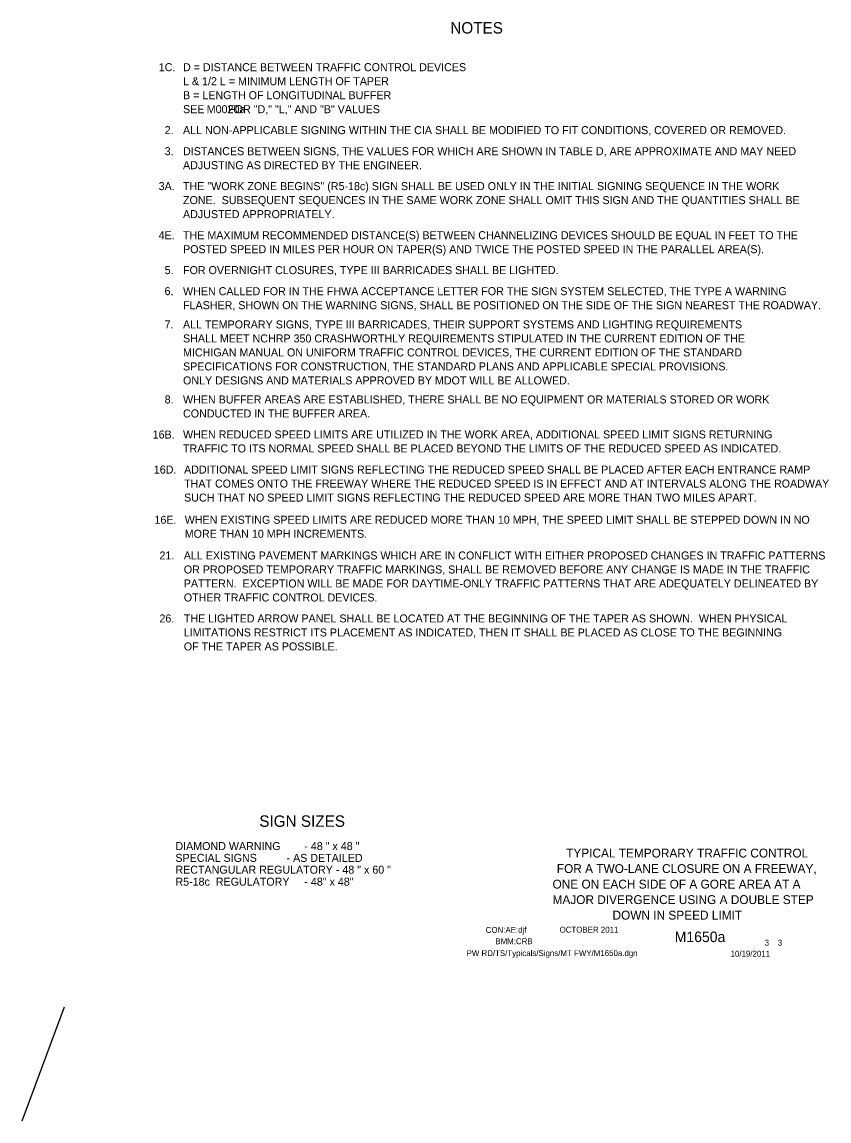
# Model space of a CAD drawing. Extents: x 16512 to 19509, y 5761 to 6974.
# Drawn here: x 18661 to 19509, y 5761 to 6914 of the extents above; entities that cross this region are included whole.
import ezdxf

# ---------------------------------------------------------------- set-up
doc = ezdxf.new("R2010")
doc.units = 0
for name, color, linetype in [('BORDER', 7, 'Continuous'), ('BORDER_SIGNAL_WO', 7, 'Continuous'), ('TYPICAL_TEXT_DIMEN_PR', 7, 'Continuous')]:
    doc.layers.add(name, color=color, linetype=linetype)

msp = doc.modelspace()

# ---------------------------------------------------------------- linework, layer by layer
at = {"layer": 'TYPICAL_TEXT_DIMEN_PR'}
msp.add_line((18705.8, 5880), (18661.5, 5760.5), dxfattribs=at)

# ---------------------------------------------------------------- texts
at = {"layer": 'BORDER'}
for s, p in [('TYPICAL TEMPORARY TRAFFIC CONTROL', (19233.2, 6037.2)), ('FOR A TWO-LANE CLOSURE ON A FREEWAY,', (19223.4, 6020.9)), ('ONE ON EACH SIDE OF A GORE AREA AT A ', (19218.9, 6004.6)), ('MAJOR DIVERGENCE USING A DOUBLE STEP ', (19218.9, 5988.3)), ('DOWN IN SPEED LIMIT', (19281.9, 5972))]:
    msp.add_text(s, height=9.3, dxfattribs=at).set_placement(p)
at = {"layer": 'BORDER_SIGNAL_WO'}
for s, height, p in [('CON:AE:djf  ', 6.2, (19148.7, 5958.1)), ('    OCTOBER 2011    ', 6.2, (19217.1, 5958.3)), ('    M1650a   ', 11, (19330.9, 5948.4)), ('BMM:CRB   ', 6.2, (19158.8, 5946.2)), (' 3    3 ', 6.2, (19439.4, 5944.7)), ('PW RD/TS/Typicals/Signs/MT FWY/M1650a.dgn      ', 6.2, (19128.6, 5933.7)), ('10/19/2011    ', 6.2, (19405.9, 5933.1))]:
    msp.add_text(s, height=height, dxfattribs=at).set_placement(p)
at = {"layer": 'TYPICAL_TEXT_DIMEN_PR'}
for s, height, p in [('NOTES', 12, (19111.5, 6902.3)), ('1C.', 8.4, (18805.2, 6862.8)), ('D = DISTANCE BETWEEN TRAFFIC CONTROL DEVICES', 8.4, (18830.7, 6862.8)), ('L & 1/2 L = MINIMUM LENGTH OF TAPER', 8.4, (18830.7, 6848.1)), ('B = LENGTH OF LONGITUDINAL BUFFER', 8.4, (18830.7, 6833.4)), ('SEE        FOR "D," "L," AND "B" VALUES', 8.4, (18830.7, 6818.7)), ('M0020a', 8.4, (18855.6, 6818.7)), ('2.', 8.4, (18811.4, 6796.7)), ('ALL NON-APPLICABLE SIGNING WITHIN THE CIA SHALL BE MODIFIED TO FIT CONDITIONS, COVERED OR REMOVED.', 8.4, (18830.7, 6796.7)), ('3.', 8.4, (18811.4, 6774.6)), ('DISTANCES BETWEEN SIGNS, THE VALUES FOR WHICH ARE SHOWN IN TABLE D, ARE APPROXIMATE AND MAY NEED', 8.4, (18830.7, 6774.6)), ('ADJUSTING AS DIRECTED BY THE ENGINEER.', 8.4, (18830.7, 6759.9)), ('3A.', 8.4, (18805.1, 6737.9)), ('THE "WORK ZONE BEGINS" (R5-18c) SIGN SHALL BE USED ONLY IN THE INITIAL SIGNING SEQUENCE IN THE WORK', 8.4, (18830.7, 6737.9)), ('ZONE.  SUBSEQUENT SEQUENCES IN THE SAME WORK ZONE SHALL OMIT THIS SIGN AND THE QUANTITIES SHALL BE', 8.4, (18830.7, 6723.2)), ('ADJUSTED APPROPRIATELY.', 8.4, (18830.7, 6708.5)), ('4E.', 8.4, (18805.1, 6686.4)), ('THE MAXIMUM RECOMMENDED DISTANCE(S) BETWEEN CHANNELIZING DEVICES SHOULD BE EQUAL IN FEET TO THE', 8.4, (18830.7, 6686.4)), ('POSTED SPEED IN MILES PER HOUR ON TAPER(S) AND TWICE THE POSTED SPEED IN THE PARALLEL AREA(S).', 8.4, (18830.7, 6671.7)), ('5.', 8.4, (18811.4, 6649.7)), ('FOR OVERNIGHT CLOSURES, TYPE III BARRICADES SHALL BE LIGHTED.', 8.4, (18830.7, 6649.7)), ('6.', 8.4, (18811.3, 6627.6)), ('WHEN CALLED FOR IN THE FHWA ACCEPTANCE LETTER FOR THE SIGN SYSTEM SELECTED, THE TYPE A WARNING ', 8.4, (18830.7, 6627.6)), ('FLASHER, SHOWN ON THE WARNING SIGNS, SHALL BE POSITIONED ON THE SIDE OF THE SIGN NEAREST THE ROADWAY.', 8.4, (18830.7, 6612.9)), ('7.', 8.4, (18811.3, 6592.7)), ('ALL TEMPORARY SIGNS, TYPE III BARRICADES, THEIR SUPPORT SYSTEMS AND LIGHTING REQUIREMENTS', 8.4, (18830.7, 6592.7)), ('SHALL MEET NCHRP 350 CRASHWORTHLY REQUIREMENTS STIPULATED IN THE CURRENT EDITION OF THE', 8.4, (18830.7, 6578)), ('MICHIGAN MANUAL ON UNIFORM TRAFFIC CONTROL DEVICES, THE CURRENT EDITION OF THE STANDARD', 8.4, (18830.7, 6563.3)), ('SPECIFICATIONS FOR CONSTRUCTION, THE STANDARD PLANS AND APPLICABLE SPECIAL PROVISIONS.', 8.4, (18830.7, 6548.6)), ('ONLY DESIGNS AND MATERIALS APPROVED BY MDOT WILL BE ALLOWED.', 8.4, (18830.7, 6533.9)), ('8.', 8.4, (18811.4, 6513.9)), ('WHEN BUFFER AREAS ARE ESTABLISHED, THERE SHALL BE NO EQUIPMENT OR MATERIALS STORED OR WORK     ', 8.4, (18830.7, 6513.9)), ('CONDUCTED IN THE BUFFER AREA.', 8.4, (18830.7, 6499.2)), ('16B.', 8.4, (18798.8, 6477.1)), ('WHEN REDUCED SPEED LIMITS ARE UTILIZED IN THE WORK AREA, ADDITIONAL SPEED LIMIT SIGNS RETURNING', 8.4, (18830.7, 6477.2)), ('TRAFFIC TO ITS NORMAL SPEED SHALL BE PLACED BEYOND THE LIMITS OF THE REDUCED SPEED AS INDICATED.', 8.4, (18830.7, 6462.5)), ('16D.', 8.4, (18800, 6440.3)), ('ADDITIONAL SPEED LIMIT SIGNS REFLECTING THE REDUCED SPEED SHALL BE PLACED AFTER EACH ENTRANCE RAMP', 8.4, (18831.8, 6440.3)), ('THAT COMES ONTO THE FREEWAY WHERE THE REDUCED SPEED IS IN EFFECT AND AT INTERVALS ALONG THE ROADWAY', 8.4, (18831.8, 6425.6)), ('SUCH THAT NO SPEED LIMIT SIGNS REFLECTING THE REDUCED SPEED ARE MORE THAN TWO MILES APART.', 8.4, (18831.8, 6410.9)), ('16E.', 8.4, (18800.7, 6387.6)), ('WHEN EXISTING SPEED LIMITS ARE REDUCED MORE THAN 10 MPH, THE SPEED LIMIT SHALL BE STEPPED DOWN IN NO', 8.4, (18832.5, 6387.6)), ('MORE THAN 10 MPH INCREMENTS.', 8.4, (18832.5, 6372.9)), ('21.', 8.4, (18805.9, 6350.1)), ('ALL EXISTING PAVEMENT MARKINGS WHICH ARE IN CONFLICT WITH EITHER PROPOSED CHANGES IN TRAFFIC PATTERNS', 8.4, (18831.5, 6350.1)), ('OR PROPOSED TEMPORARY TRAFFIC MARKINGS, SHALL BE REMOVED BEFORE ANY CHANGE IS MADE IN THE TRAFFIC', 8.4, (18831.5, 6335.4)), ('PATTERN.  EXCEPTION WILL BE MADE FOR DAYTIME-ONLY TRAFFIC PATTERNS THAT ARE ADEQUATELY DELINEATED BY', 8.4, (18831.5, 6320.7)), ('OTHER TRAFFIC CONTROL DEVICES.', 8.4, (18831.5, 6306)), ('26.', 8.4, (18805.9, 6284)), ('THE LIGHTED ARROW PANEL SHALL BE LOCATED AT THE BEGINNING OF THE TAPER AS SHOWN.  WHEN PHYSICAL', 8.4, (18831.5, 6284)), ('LIMITATIONS RESTRICT ITS PLACEMENT AS INDICATED, THEN IT SHALL BE PLACED AS CLOSE TO THE BEGINNING', 8.4, (18831.5, 6269.3)), ('OF THE TAPER AS POSSIBLE.', 8.4, (18831.5, 6254.6)), ('SIGN SIZES', 12, (18910.8, 6069.4)), ('DIAMOND WARNING        - 48 " x 48 "', 8.4, (18822.7, 6045)), ('SPECIAL SIGNS          - AS DETAILED', 8.4, (18822.7, 6032.6)), ('RECTANGULAR REGULATORY - 48 " x 60 "', 8.4, (18822.7, 6020.2)), ('R5-18c  REGULATORY     - 48" x 48"', 8.4, (18822.7, 6007.6))]:
    msp.add_text(s, height=height, dxfattribs=at).set_placement(p)

doc.saveas('drawing.dxf')
